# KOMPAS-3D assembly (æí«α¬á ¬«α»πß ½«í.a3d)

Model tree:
1. Эскиз:1
2. Операция выдавливания:1
     Расстояние 1 = 0.3; Расстояние 2 = 1.1
3. Скругление:1
     Радиус = 0.1
4. Эскиз:2
5. Операция выдавливания:2
     Расстояние 1 = 1; Расстояние 2 = 1.1
6. Скругление:2
     Радиус = 0.2
7. Эскиз:3
8. Операция выдавливания:3
     Расстояние 1 = 0.5; Расстояние 2 = 1.1

Referenced files in D:\МОДЕЛЬ ТАНКА Т90\ДЕТАЛИ\КОРПУС\МЕТАЛЛ\КОРПУС ШТАМПОВКА\: корпус лобовая.m3d
Referenced files in D:\МОДЕЛЬ ТАНКА Т90\ДЕТАЛИ\КОРПУС\МЕТАЛЛ\КОРПУС ШТАМПОВКА\ПЛАСТИК\: пластик лоб.m3d
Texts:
  Сборка корпус лоб  с пластиком
  stalker61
